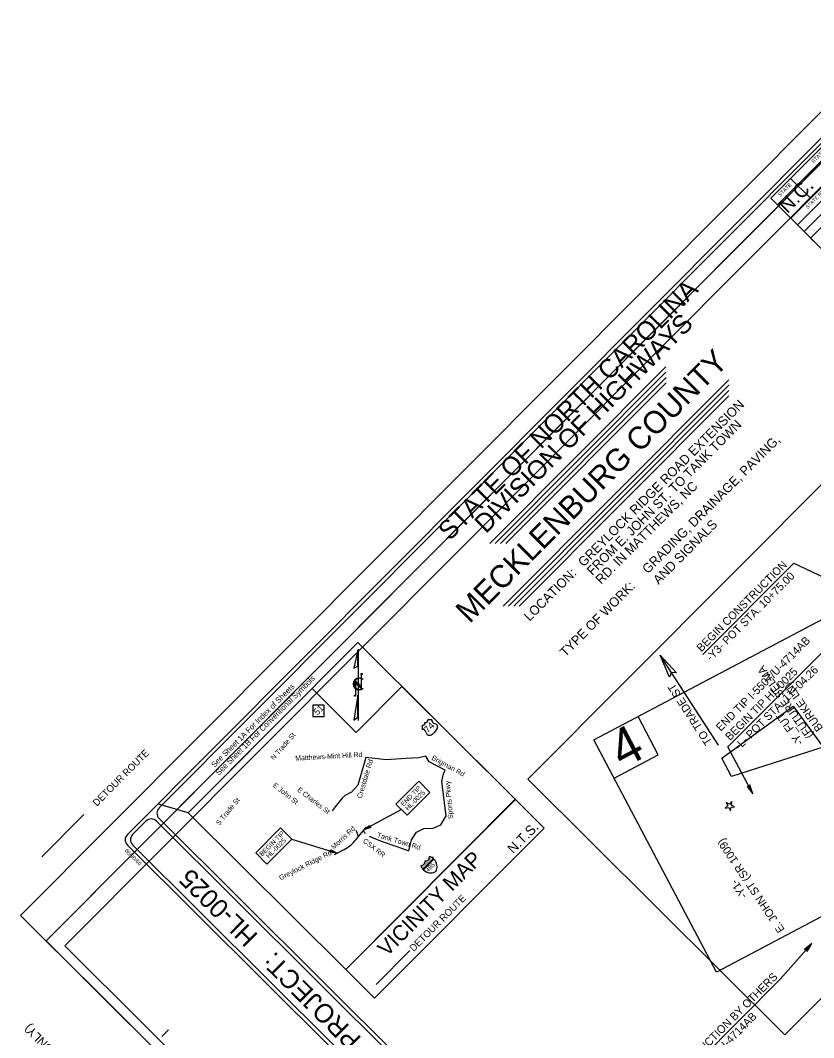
# Model space of a CAD drawing. Extents: x 1481763 to 1495577, y 493394 to 506245.
# Drawn here: x 1484916 to 1488088, y 497417 to 501486 of the extents above; entities that cross this region are included whole.
import ezdxf

# ---------------------------------------------------------------- set-up
doc = ezdxf.new("R2010")
doc.units = 0
for name, color, linetype in [('Default', 7, 'Continuous'), ('Old_Level_4', 7, 'Continuous'), ('Prop Dimension', 7, 'Continuous'), ('Prop DSN Text', 7, 'Continuous'), ('Prop DSN White Annotation Label', 7, 'Continuous'), ('Prop Grid Mask', 7, 'Continuous'), ('Prop Horizontal Alignment', 7, 'Continuous'), ('Prop Horizontal Alignment Station Label', 7, 'Continuous'), ('Prop PHM Highway Shield CELL', 7, 'Continuous'), ('Prop RDY Traffic Signal CELL', 7, 'Continuous'), ('Prop Terminator CELL', 7, 'Continuous'), ('Scratch_Level_0', 7, 'Continuous'), ('Scratch_Level_1', 7, 'Continuous'), ('Scratch_Level_4', 7, 'Continuous'), ('Sheet Cutting Line CELL', 7, 'Continuous'), ('Sheet Data Field CELL', 7, 'Continuous'), ('Sheet North Arrow CELL', 7, 'Continuous'), ('Sheet Plot Border Inside CELL', 7, 'Continuous'), ('Sheet Plot Border Outside CELL', 7, 'Continuous'), ('Sheet Sticker Incomplete CELL', 7, 'Continuous'), ('Sheet Title CELL', 7, 'Continuous')]:
    doc.layers.add(name, color=color, linetype=linetype)

msp = doc.modelspace()

# ---------------------------------------------------------------- linework, layer by layer
at = {"layer": 'Default'}
msp.add_line((1485170.6, 498309.5), (1485002.6, 498140.8), dxfattribs=at)
at = {"layer": 'Old_Level_4'}
msp.add_line((1486338.4, 497629.4), (1486473.9, 497765.5), dxfattribs=at)
msp.add_lwpolyline([(1486311.4, 498223.1), (1486358.7, 498202.6), (1486421.6, 498181.3), (1486469.6, 498165), (1486480.4, 498208.1), (1486500.7, 498239.1), (1486529.5, 498253.5), (1486566.7, 498255.5), (1486597.7, 498267.9), (1486618.5, 498304.9), (1486601.8, 498442.2), (1486607.5, 498472.4), (1486615, 498486.7), (1486551.1, 498520.6), (1486537.1, 498543.3), (1486508.8, 498536.5), (1486458.5, 498533.4), (1486378.8, 498528.5), (1486333, 498533.2), (1486297.9, 498538.3), (1486265.7, 498427.8), (1486239.8, 498399.2), (1486216.8, 498387), (1486202.9, 498374.8), (1486175.4, 498340.5), (1486162.3, 498324.5)], dxfattribs=at)
at = {"layer": 'Prop Dimension'}
for p, q in [((1488009, 499315.3), (1487644.9, 498949.7)), ((1488009, 499315.3), (1488423.2, 499117.7)), ((1488142.6, 498979.2), (1487745.2, 498580.2)), ((1487844.4, 498392.9), (1487745.2, 498580.2)), ((1487954.1, 497650.7), (1488080.4, 497793.4)), ((1487954.1, 497650.7), (1487527.6, 497222.4))]:
    msp.add_line(p, q, dxfattribs=at)
at = {"layer": 'Prop DSN Text'}
for p, q in [((1487707.1, 498587.7), (1487474, 498947.7)), ((1486440.3, 498329.3), (1486289.6, 498248)), ((1486001.6, 498211.4), (1486183.4, 498155.8))]:
    msp.add_line(p, q, dxfattribs=at)
msp.add_lwpolyline([(1486217.1, 497689.6), (1486895.2, 498370.5), (1487010.5, 498255.7), (1486332.4, 497574.8)], close=True, dxfattribs=at)
at = {"layer": 'Prop DSN White Annotation Label'}
msp.add_lwpolyline([(1487208.7, 498608.1), (1488222.1, 499143.2), (1488965.4, 498493.7), (1489025.4, 498380), (1487698.9, 497679.6)], close=True, dxfattribs=at)
msp.add_lwpolyline([(1487289.7, 498454.6), (1487466.6, 498548.1), (1487385.6, 498701.5)], dxfattribs=at)
at = {"layer": 'Prop Grid Mask'}
for points in [[(1486417.8, 498351.7), (1486508.8, 498443.1), (1486553.8, 498398.3), (1486462.8, 498307)], [(1485857.4, 498156.2), (1485956.9, 498256.1), (1486001.9, 498211.3), (1485902.4, 498111.4)]]:
    msp.add_lwpolyline(points, close=True, dxfattribs=at)
at = {"layer": 'Prop Horizontal Alignment'}
for p, q in [((1486259.1, 498210.2), (1486298.3, 498258.8)), ((1486263.4, 498234.1), (1486263.3, 498234.8)), ((1486290.8, 498239.9), (1486291.5, 498238.4)), ((1486172.4, 498150), (1486210.7, 498170.3))]:
    msp.add_line(p, q, dxfattribs=at)
for centre, radius, start, end in [((1486247.7, 498234), 15.6, 2.8235, 50.7272), ((1486279.8, 498234.2), 16.4, 180.3319, 227.5042), ((1486278.7, 498235.1), 13, 21.6462, 49.5197), ((1486302.8, 498244.7), 12.9, 208.8639, 235.4773), ((1486137.9, 498307.9), 155.7, 297.895, 321.1156)]:
    msp.add_arc(centre, radius, start, end, dxfattribs=at)
at = {"layer": 'Prop PHM Highway Shield CELL'}
for p, q in [((1486130.4, 498746.7), (1486085.3, 498747.1)), ((1486085.3, 498747.1), (1486085.4, 498701.5)), ((1486130.5, 498702.1), (1486130.4, 498746.7)), ((1486085.4, 498701.5), (1486130.5, 498702.1)), ((1486561.2, 498688.7), (1486545.3, 498688.5)), ((1486522.5, 498665.8), (1486522.5, 498649.9)), ((1486567.4, 498133.7), (1486525.4, 498091.5)), ((1486525.5, 498091.6), (1486567.4, 498133.7)), ((1486569.7, 498131.5), (1486527.5, 498089.1)), ((1486527.5, 498089.1), (1486569.7, 498131.5)), ((1486589.6, 498124.1), (1486589.5, 498124)), ((1486589.6, 498124.1), (1486589.5, 498124)), ((1486589.5, 498124), (1486589.6, 498124.1))]:
    msp.add_line(p, q, dxfattribs=at)
for centre, radius, start, end in [((1486523.2, 498676.4), 10.6, 266.1975, 4.6682), ((1486534.8, 498687.8), 10.6, 265.569, 4.108), ((1486575.7, 498687.3), 14.5, 174.6433, 256.9786), ((1486523.8, 498635.5), 14.5, 13.2587, 95.1575), ((1486551.7, 498640.4), 13.8, 186.662, 285.7164), ((1486547, 498654.2), 28.4, 287.4324, 321.0045), ((1486572.5, 498634.2), 4.03, 81.6193, 148.6808), ((1486570.9, 498659.4), 13.8, 344.5208, 83.5807), ((1486577.1, 498638.7), 4.03, 121.5524, 186.2514), ((1486557, 498664.1), 28.4, 309.2442, 342.8049), ((1486517.9, 498123), 16.8, 267.4184, 3.9692), ((1486535.8, 498140.9), 16.8, 266.268, 2.8189), ((1486540.1, 498101.2), 42.4, 49.933, 72.9434), ((1486540.1, 498101.2), 42.4, 45.6712, 49.9313), ((1486540.1, 498101.2), 42.4, 332.3215, 45.6591), ((1486557.7, 498118.9), 42.4, 197.294, 220.283), ((1486557.7, 498118.9), 42.4, 220.3043, 224.5656), ((1486557.7, 498118.9), 42.4, 224.5841, 297.9157)]:
    msp.add_arc(centre, radius, start, end, dxfattribs=at)
at = {"layer": 'Prop RDY Traffic Signal CELL'}
msp.add_lwpolyline([(1487744.7, 498345.3), (1487734.4, 498335), (1487748.8, 498337.3), (1487755.4, 498324.4), (1487757.6, 498338.7), (1487772, 498341), (1487759, 498347.6), (1487761.3, 498361.9), (1487751, 498351.6), (1487738, 498358.2), (1487744.7, 498345.3)], dxfattribs=at)
at = {"layer": 'Prop Terminator CELL'}
for points in [[(1487511.7, 498859.5), (1487474, 498947.7), (1487539.8, 498877), (1487519.1, 498878)], [(1487822.1, 498421.8), (1487844.4, 498392.9), (1487833.1, 498427.9), (1487829.6, 498420.8)], [(1486317.3, 498257.3), (1486289.6, 498248), (1486312.6, 498266.2), (1486311.8, 498260)], [(1486157.3, 498169), (1486183.4, 498155.8), (1486154.2, 498159.4), (1486159.3, 498163.2)], [(1488061.2, 497762.3), (1488080.4, 497793.4), (1488051.6, 497770.5), (1488059.5, 497769.8)]]:
    msp.add_lwpolyline(points, close=True, dxfattribs=at)
at = {"layer": 'Scratch_Level_1'}
for points in [[(1486441.9, 498821.9), (1486895.2, 498370.5), (1486217.1, 497689.6), (1485587.2, 498316.9), (1486082.4, 498814.2), (1486259, 498638.3)], [(1486441.9, 498821.9), (1486895.4, 498370.4), (1486217.3, 497689.5), (1485587.4, 498316.8), (1486082.5, 498814.1), (1486259, 498638.3)]]:
    msp.add_lwpolyline(points, close=True, dxfattribs=at)
at = {"layer": 'Scratch_Level_4'}
msp.add_line((1485587.2, 498316.9), (1485468.7, 498351.8), dxfattribs=at)
for points in [[(1486945.7, 498451.8), (1488980.9, 500495.4), (1490008.1, 499472.4), (1487973, 497428.8)], [(1487759, 498462.3), (1487720.6, 498534.8), (1488006.4, 498743.3), (1488126.2, 498579.3)]]:
    msp.add_lwpolyline(points, close=True, dxfattribs=at)
at = {"layer": 'Sheet Cutting Line CELL'}
for q in [(1488584.2, 501383.6), (1487357.7, 495475.3)]:
    msp.add_line((1485019.4, 497803.9), q, dxfattribs=at)
msp.add_lwpolyline([(1485019.4, 497803.9), (1488584.2, 501383.6), (1490922.5, 499055), (1487357.7, 495475.3)], close=True, dxfattribs=at)
at = {"layer": 'Sheet North Arrow CELL'}
for p, q in [((1486267.6, 498686.4), (1486267.8, 498970.9)), ((1486256.7, 498844.4), (1486256.6, 498785)), ((1486278.4, 498822.6), (1486256.7, 498844.4)), ((1486278.4, 498820.5), (1486256.7, 498842.2)), ((1486256.7, 498842.2), (1486256.7, 498836.9)), ((1486278.4, 498871.9), (1486278.4, 498813.5)), ((1486286.5, 498850.1), (1486286.8, 498849.9)), ((1486278.4, 498815.1), (1486256.7, 498836.9)), ((1486256.7, 498836.9), (1486278.4, 498815.1)), ((1486278.4, 498813.5), (1486256.7, 498835.3)), ((1486278.4, 498815.1), (1486278.4, 498820.5))]:
    msp.add_line(p, q, dxfattribs=at)
for points in [[(1486265.8, 498968.4), (1486249.5, 498894.5), (1486265.8, 498902.8)], [(1486265.3, 498786.7), (1486249.2, 498686.5), (1486265.3, 498699.1)]]:
    msp.add_lwpolyline(points, close=True, dxfattribs=at)
for centre in [(1486280.8, 498871.8), (1486254.3, 498785)]:
    msp.add_circle(centre, 2.32, dxfattribs=at)
for centre, radius, start, end in [((1486270.7, 498832.2), 23.9, 47.7961, 312.3501), ((1486273, 498832.2), 22.4, 53.0511, 308.5848)]:
    msp.add_arc(centre, radius, start, end, dxfattribs=at)
at = {"layer": 'Sheet Plot Border Inside CELL'}
msp.add_lwpolyline([(1487337.5, 495550.5), (1490865.3, 499093), (1488622.4, 501326.5), (1485094.6, 497784)], close=True, dxfattribs=at)
at = {"layer": 'Sheet Plot Border Outside CELL'}
msp.add_lwpolyline([(1488481.3, 501486.1), (1484916.4, 497906.4), (1487254.7, 495577.9), (1490819.6, 499157.6)], close=True, dxfattribs=at)
at = {"layer": 'Sheet Title CELL'}
for p, q in [((1486793.1, 499393.2), (1487497.5, 500100.5)), ((1486814.3, 499393.3), (1487497.5, 500079.3)), ((1486835.5, 499393.3), (1487497.6, 500058.1)), ((1486846.5, 499142.5), (1487748.3, 500048)), ((1486856.7, 499393.3), (1487497.6, 500036.9)), ((1486867.7, 499142.5), (1487748.4, 500026.8)), ((1486889, 499142.5), (1487748.4, 500005.6)), ((1486910.2, 499142.6), (1487748.5, 499984.4)), ((1487629, 496123.8), (1485460.8, 498283.1)), ((1487246.4, 496526.1), (1485471.4, 498293.7)), ((1485481.7, 497421.8), (1485508.2, 497448.4)), ((1485481.7, 497421.8), (1485508.2, 497448.4))]:
    msp.add_line(p, q, dxfattribs=at)
for points in [[(1488477.3, 501375.9), (1485344.2, 498229.8)], [(1488477.3, 501354.6), (1485471.3, 498336.1)], [(1488498.5, 501358.9), (1487916.4, 500774.3), (1488235.2, 500456.8)], [(1488578.2, 501279.5), (1487996.1, 500695), (1487942.9, 500747.9), (1488525.1, 501332.5)], [(1488631.4, 501226.6), (1488049.2, 500642), (1488022.7, 500668.5), (1488604.8, 501253.1)], [(1488190.1, 500889.8), (1488075.5, 500774.7), (1487995.7, 500854.1), (1488339.8, 501199.5)], [(1488102.3, 500589.1), (1488075.8, 500615.6), (1488657.9, 501200.2)], [(1485418.4, 498282.9), (1485365.4, 498229.8)], [(1485344.3, 498187.4), (1487533.8, 496006.9)], [(1485344.3, 498187.4), (1487533.8, 496006.9)], [(1485365.6, 498187.4), (1487533.8, 496028.2)]]:
    msp.add_lwpolyline(points, dxfattribs=at)
for points in [[(1486895.2, 498370.5), (1486217.1, 497689.6), (1485587.2, 498316.9), (1486265.2, 498997.8)], [(1485587.2, 498316.9), (1486082.4, 498814.2), (1486259, 498638.3), (1486441.9, 498821.9), (1486895, 498370.6), (1486217, 497689.7)], [(1486217.1, 497689.6), (1486895.2, 498370.5), (1487010.5, 498255.7), (1486332.4, 497574.8)]]:
    msp.add_lwpolyline(points, close=True, dxfattribs=at)
for centre, start, end in [((1485492.5, 498315), 135.1191, 225.1191), ((1485439.5, 498261.9), 45.1191, 135.1191), ((1485365.4, 498208.7), 135.1191, 225.1191), ((1485386.6, 498208.8), 135.1191, 225.1191)]:
    msp.add_arc(centre, 30, start, end, dxfattribs=at)

# ---------------------------------------------------------------- texts
at = {"layer": 'Default'}
for s, rotation, p in [('N Trade St', 48.7859, (1485929.9, 498525.9)), ('Matthews-Mint Hill Rd', 3.2578, (1486016, 498525.1)), ('Crestdale Rd', 73.2593, (1486280.6, 498372.7)), ('Brigman Rd', 331.0422, (1486558.5, 498530.8)), ('E John St', 321.3901, (1485924, 498423.2)), ('Sports Pkwy', 95.0366, (1486646.3, 498292.5)), ('E Charles St', 322.4571, (1486021.4, 498405.2)), ('S Trade St', 50.5492, (1485711.6, 498264.9)), ('Morris Rd', 43.598, (1486170.5, 498168.5)), ('Tank Town Rd', 343.3292, (1486340.5, 498219.3)), ('CSX RR', 322.4571, (1486283.6, 498200.3)), ('Greylock Ridge Rd', 26.8476, (1485956.8, 498046.1))]:
    msp.add_text(s, height=20, rotation=rotation, dxfattribs=at).set_placement(p)
at = {"layer": 'Old_Level_4'}
for s, height, p in [('N.T.S.', 39.2, (1486886.8, 498150.5)), ('DETOUR ROUTE', 28, (1486489, 497759.6))]:
    msp.add_text(s, height=height, rotation=45.1191, dxfattribs=at).set_placement(p)
at = {"layer": 'Prop DSN Text'}
for s, height, rotation, p in [('BEGIN CONSTRUCTION', 32, 45.1191, (1487638.9, 498958.4)), ('-Y3- POT STA. 10+75.00', 32, 45.1191, (1487676.3, 498921.1)), ('END TIP I-5507/U-4714AB', 32, 45.1191, (1487716, 498640.4)), ('BEGIN TIP HL-0025', 32, 45.1191, (1487753.4, 498603.2)), ('-L- POT STA. 11+04.26', 32, 45.1191, (1487790.8, 498565.9)), ('TO TRADE ST', 32, 122.9223, (1487682.9, 498599.7)), ('4', 150, 27.8403, (1487323.1, 498491.2)), ('DETOUR ROUTE', 28, 45.1191, (1485222.5, 498340.7)), ('END TIP', 18.93, 45.1327, (1486447.7, 498340.9)), ('HL-0025', 18.93, 45.1327, (1486466.1, 498324.3)), ('BEGIN TIP', 18.93, 45.1327, (1485882.9, 498141)), ('HL-0025', 18.93, 45.1327, (1485910, 498133)), ('VICINITY MAP', 61.25, 45.1191, (1486381.9, 497738.5)), ('CONSTRUCTION BY OTHERS', 32, 45.1191, (1487520.2, 497229.8)), ('TIP I-5507 / U-4714AB', 32, 45.1191, (1487557.7, 497192.5))]:
    msp.add_text(s, height=height, rotation=rotation, dxfattribs=at).set_placement(p)
at = {"layer": 'Prop Horizontal Alignment Station Label'}
for s, p in [('E. JOHN ST (SR 1009)', (1487973.4, 497849.9)), ('-Y1-', (1487824, 497986.4))]:
    msp.add_text(s, height=32, rotation=123.8699, dxfattribs=at).set_placement(p)
at = {"layer": 'Prop PHM Highway Shield CELL'}
for s, height, p in [('51', 26.25, (1486104.5, 498705.1)), ('74', 27.5, (1486545.7, 498633.8)), ('INTERSTATE', 7.5, (1486526.1, 498094.3)), ('485', 17.47, (1486547.3, 498078.5))]:
    msp.add_text(s, height=height, rotation=45.1186, dxfattribs=at).set_placement(p)
at = {"layer": 'Scratch_Level_0'}
for s, p in [('(FUTURE SELMA ', (1488087.7, 498627.8)), ('BURKE LN)', (1488126.8, 498655.8)), ('-Y_FUT-', (1488048.7, 498599.9))]:
    msp.add_text(s, height=32, rotation=125.5902, dxfattribs=at).set_placement(p)
at = {"layer": 'Sheet Data Field CELL'}
for s, height, p in [('MECKLENBURG COUNTY', 90, (1486712.2, 499070.9)), ('GREYLOCK RIDGE ROAD EXTENSION', 37.5, (1487168.4, 499298.1)), ('FROM E. JOHN ST. TO TANK TOWN ', 37.5, (1487203.3, 499263.4)), ('GRADING, DRAINAGE, PAVING, ', 37.5, (1487424.8, 499270.5)), ('RD. IN MATTHEWS, NC', 37.5, (1487238.1, 499228.7)), ('AND SIGNALS', 37.5, (1487468, 499227.5))]:
    msp.add_text(s, height=height, rotation=45.1191, dxfattribs=at).set_placement(p)
at = {"layer": 'Sheet Sticker Incomplete CELL'}
msp.add_text('(FOR INFORMATION ONLY)', height=35.009, rotation=135.1191, dxfattribs=at).set_placement((1485385.4, 497043.2))
at = {"layer": 'Sheet Title CELL'}
for s, height, rotation, p in [('STATE PROJECT REFERENCE NO.', 14.999, 45.1191, (1488087.6, 500913.3)), ('STATE', 15, 45.1191, (1487954.5, 500779.7)), ('N.C.', 58.05, 45.1191, (1487983.1, 500711.1)), ('STATE PROJ. NO.', 14.4, 45.1191, (1488064.1, 500730.7)), ('STATE OF NORTH CAROLINA', 75, 45.1191, (1486632.4, 499401.7)), ('DIVISION OF HIGHWAYS', 75, 45.1191, (1486777.4, 499430.4)), ('LOCATION: ', 37.5, 45.1191, (1486952, 499080.6)), ('TYPE OF WORK:', 37.5, 45.1191, (1487095.5, 498937.7)), ('See Sheet 1B For Conventional Symbols', 22.5, 45.1191, (1485710.4, 498464.6)), ('See Sheet 1A For Index of Sheets', 22.5, 45.1191, (1485692.8, 498496)), ('09/08/99', 15.75, 135.1191, (1485403.1, 498115.1)), ('HL-0025', 75, 135.1191, (1485870.2, 497827.1)), ('TIP PROJECT:', 75, 135.1191, (1486413.5, 497286.1))]:
    msp.add_text(s, height=height, rotation=rotation, dxfattribs=at).set_placement(p)

doc.saveas('drawing.dxf')
